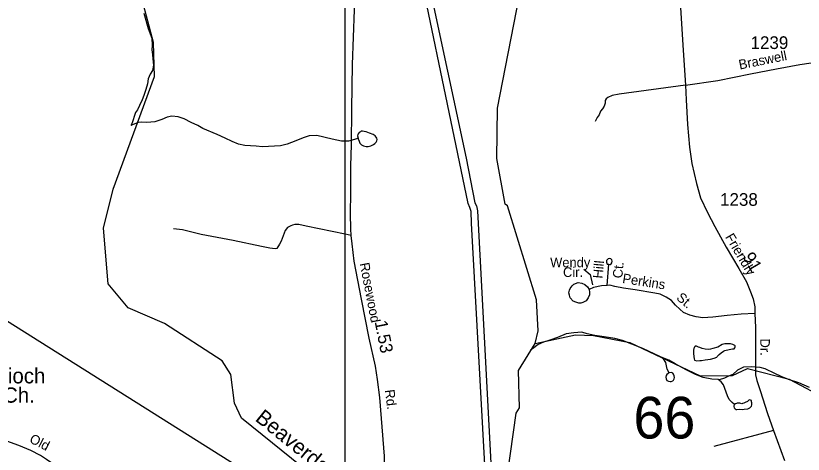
# Model space of a CAD drawing. Extents: x 2206922 to 2357709, y 510027 to 673830.
# Drawn here: x 2263859 to 2271615, y 598510 to 602827 of the extents above; entities that cross this region are included whole.
import ezdxf

# ---------------------------------------------------------------- set-up
doc = ezdxf.new("R2010")
doc.units = 0
for name, color, linetype in [('Exist Cultural Church Label', 7, 'Continuous'), ('Exist Hydrographic Creek Single Shore', 7, 'Continuous'), ('Exist Hydrographic Creek Single Shore Label', 7, 'Continuous'), ('Exist Hydrographic Misc Water Feature', 7, 'Continuous'), ('Exist Road Non-System Type 51', 7, 'Continuous'), ('Exist Road Non-System Type 51 Label', 7, 'Continuous'), ('Exist Road Secondary Mileage Hundredths English Label', 7, 'Continuous'), ('Exist Road Secondary Structure Standard Bridge Number Label', 7, 'Continuous'), ('Exist Road Secondary Type 51 Attributed', 7, 'Continuous'), ('Exist Road Secondary Type 51 Label', 7, 'Continuous'), ('Exist Road Secondary Type 51 Number Label', 7, 'Continuous'), ('Exist Utilities Electrical Transmission Line', 7, 'Continuous'), ('Map Preparation Inset Cut Line', 7, 'Continuous')]:
    doc.layers.add(name, color=color, linetype=linetype)

msp = doc.modelspace()

# ---------------------------------------------------------------- linework, layer by layer
at = {"layer": 'Exist Hydrographic Creek Single Shore'}
for points in [[(2268973.5, 599599.1), (2269005.5, 599726.3), (2268986.6, 600031.7), (2268702.4, 600955.8), (2268677.6, 600972.7), (2268598.4, 601420.4), (2268602.5, 601918.8), (2268816.4, 603013.1), (2268831.6, 603239.1), (2269622.5, 605046.5), (2269645.4, 605219.9)], [(2266778.4, 598305.4), (2266082.5, 598864), (2266014.4, 599013), (2265978.5, 599295.8), (2265893.4, 599428.7), (2265323.6, 599797.7), (2264964.5, 599952.6), (2264770.5, 600186.1), (2264723.4, 600734.7), (2264819.5, 601119.8), (2265225.5, 602229.9), (2265214.5, 602564.7), (2265102.5, 602986.8), (2264730.3, 603601), (2264265.5, 604253.3), (2264229.6, 604503.2), (2264227.3, 604543.3), (2264259.3, 604664.6), (2264265, 604700), (2264253.6, 604725.2), (2264185.5, 604769.8), (2264051.4, 604893.9), (2263717.4, 605022)], [(2268973.5, 599599.1), (2269372.5, 599686.1), (2269547.4, 599679.3), (2269906.5, 599609.7), (2270600.6, 599280.8), (2270917.6, 599284.2), (2271066.4, 599353.3), (2271475.5, 599249.9), (2272245.5, 598840.8)], [(2268671.4, 598096.6), (2268788.5, 598914.1), (2268821.5, 598965.9), (2268809.4, 599333.5), (2268973.5, 599599.1)]]:
    msp.add_lwpolyline(points, dxfattribs=at)
at = {"layer": 'Exist Hydrographic Misc Water Feature'}
for points in [[(2265121.6, 602854), (2265163.2, 602700.6), (2265183.1, 602648.9), (2265197.9, 602604.9), (2265202.4, 602534.9), (2265200.7, 602493), (2265205.2, 602445.2), (2265209.7, 602403.2), (2265214.3, 602341.3), (2265204.6, 602289.2), (2265182.9, 602252.7), (2265163.4, 602206.6), (2265158.1, 602156.7), (2265140.6, 602100.5), (2265119.1, 602042.6), (2265105.2, 602000.4), (2265078.1, 601942.1), (2265058.2, 601902.1), (2265036.9, 601875.7), (2265001.6, 601763.4), (2264993.8, 601747.5)], [(2267232, 601622.7), (2267219.9, 601618.5), (2267216.2, 601616.6), (2267203.9, 601612.3), (2267172.1, 601602.1), (2267136.2, 601593.7), (2267100.1, 601591.4), (2267068.1, 601593), (2266974, 601612.1), (2266825.8, 601648.6), (2266749.7, 601643.9), (2266690.2, 601623.6), (2266618.3, 601596.8), (2266530.9, 601562.1), (2266466.9, 601545.4), (2266289.3, 601535.7), (2266225.2, 601543.3), (2266115.5, 601548.1), (2266053.1, 601561.6), (2265990.8, 601588.7), (2265922.9, 601622.1), (2265842.1, 601657.4), (2265701.9, 601716.3), (2265653.7, 601745.8), (2265585.4, 601775.2), (2265516.7, 601812.3), (2265458.9, 601832), (2265395.1, 601837.1), (2265349, 601828.6), (2265297.3, 601806), (2265229.4, 601783.8), (2265149.3, 601774.8), (2265099.6, 601780.3), (2265063.5, 601776), (2264993.8, 601747.5)], [(2267232, 601622.7), (2267232, 601614.6), (2267240.2, 601592.7), (2267246.7, 601572.6), (2267252.7, 601564.8), (2267264.4, 601557), (2267284.5, 601547), (2267308.7, 601541.4), (2267328.8, 601539.6), (2267356.4, 601548), (2267370.2, 601554), (2267382.5, 601558.3), (2267396.2, 601570), (2267410.2, 601582.5), (2267413.9, 601594.5), (2267418, 601608.5), (2267413.6, 601620.5), (2267407.5, 601630.3), (2267397.7, 601644.4), (2267387.4, 601652), (2267377.8, 601657.9), (2267343.5, 601671.6), (2267309.3, 601683.3), (2267289, 601689.1), (2267273.2, 601691.1), (2267261.3, 601690.9), (2267253.5, 601684.7), (2267241.4, 601676.8), (2267231.4, 601664.5), (2267227.5, 601656.6), (2267226, 601644.7), (2267232, 601622.7)], [(2270232.7, 599457.9), (2270208.9, 599470), (2270035.9, 599552), (2269835.1, 599630.1), (2269759.2, 599649.6), (2269652.8, 599666.5), (2269561.2, 599679.5), (2269485.1, 599695), (2269434.8, 599712.3), (2269355.1, 599705.7), (2269281.1, 599695), (2269193.3, 599658.3), (2269117.8, 599633.6), (2269058, 599613), (2269004.4, 599590.3), (2268948.5, 599548), (2268924.9, 599533.7)], [(2270649, 599438.1), (2270702.7, 599446.6), (2270736.7, 599456.9), (2270762.6, 599467.2), (2270766.3, 599471.2), (2270786.6, 599493.2), (2270807.9, 599509.4), (2270827.8, 599523.5), (2270841.9, 599531.9), (2270883.5, 599540.3), (2270919.4, 599546.6), (2270933.4, 599548.6), (2270939.5, 599556.6), (2270943.4, 599564.9), (2270945.3, 599576.8), (2270941.4, 599580.6), (2270933.6, 599584.6), (2270921.3, 599590.5), (2270897.1, 599596.2), (2270871, 599598.1), (2270842.9, 599597.9), (2270817.3, 599591.6), (2270773.4, 599563.3), (2270725.4, 599550.7), (2270701.9, 599544.5), (2270677.7, 599542), (2270650, 599545.8), (2270619.8, 599551.6), (2270597.3, 599559.4), (2270583.3, 599565.2), (2270563.5, 599573.1), (2270551.6, 599572.9), (2270545.8, 599568.9), (2270539.7, 599564.9), (2270534.1, 599534.9), (2270534.1, 599498.8), (2270540.7, 599448.7), (2270544.8, 599435.2), (2270566.5, 599431.1), (2270594.6, 599431.3), (2270613.1, 599433.8), (2270649, 599438.1)], [(2270294.2, 599310.7), (2270275.8, 599346.3), (2270261.2, 599412.2), (2270232.7, 599457.9)], [(2270776.7, 599245.3), (2270714.8, 599248.6), (2270628.5, 599264), (2270552.6, 599295.3), (2270467.9, 599338.5), (2270353.1, 599399.2), (2270289.3, 599434.8), (2270232.7, 599457.9)], [(2271675, 599167.9), (2271572.5, 599213), (2271470, 599245.8), (2271397.8, 599275), (2271335.7, 599304.6), (2271241.2, 599349.7), (2271191.1, 599363.3), (2271105.2, 599372.2), (2271025.2, 599367.6), (2270965.8, 599338.9), (2270922.3, 599294.8), (2270877.8, 599278.3), (2270840.3, 599260), (2270786.6, 599243.4), (2270776.7, 599245.3)], [(2270294.2, 599310.7), (2270284.2, 599304.5), (2270270, 599296.5), (2270264.7, 599284.3), (2270260.6, 599270.4), (2270264.9, 599252.3), (2270272.5, 599234.5), (2270288.9, 599228.8), (2270303, 599226.6), (2270312.9, 599226.8), (2270328.9, 599232.9), (2270337.1, 599239), (2270342.8, 599253.1), (2270346.5, 599265.1), (2270342.4, 599281.2), (2270338.1, 599297.2), (2270329.9, 599309), (2270316, 599314.7), (2270298.3, 599313), (2270294.2, 599310.7)], [(2270936.6, 598999), (2270914.5, 599018.5), (2270886.2, 599048.3), (2270870.2, 599084.4), (2270828.8, 599193.6), (2270806.6, 599223.8), (2270776.7, 599245.3)], [(2270936.6, 598999), (2270932.5, 598987), (2270931.1, 598980.7), (2270933.2, 598967), (2270943, 598957), (2270953.5, 598951), (2270961.1, 598949), (2270983.2, 598953.4), (2271012.9, 598951.8), (2271033, 598954), (2271068.9, 598958.3), (2271081, 598962.2), (2271089, 598966.3), (2271096.8, 598974.4), (2271104.8, 598982.5), (2271108.9, 598996.5), (2271108.3, 599016.4), (2271106.6, 599024.4), (2271106, 599030.6), (2271104.4, 599038.5), (2271094.3, 599042.5), (2271088.4, 599044.2), (2271080.4, 599042.2), (2271074.2, 599038.2), (2271066.4, 599030.1), (2271042.7, 599019.9), (2271028.5, 599013.9), (2271016.6, 599009.6), (2271008.6, 599007.6), (2270998.4, 599009.5), (2270990.6, 599013.5), (2270980.3, 599013.5), (2270962.5, 599011.3), (2270956.5, 599011), (2270946.5, 599007.2), (2270936.6, 598999)]]:
    msp.add_lwpolyline(points, dxfattribs=at)
at = {"layer": 'Exist Road Non-System Type 51'}
for p, q in [((2267163.1, 600664.5), (2267104.4, 600676.5)), ((2269682.3, 600172.5), (2269700.4, 600380.5)), ((2271321.5, 598744.4), (2270734.7, 598585.3))]:
    msp.add_line(p, q, dxfattribs=at)
for points in [[(2270453.5, 602142.7), (2269800.7, 602054.6), (2269732.7, 602042), (2269690.9, 602023.7), (2269675, 602009.4), (2269665.3, 601991.4), (2269663.6, 601967.4), (2269653.8, 601937.2), (2269638, 601909.2), (2269618.4, 601887), (2269604.7, 601850.9), (2269585, 601826.7), (2269565.3, 601784.5)], [(2267104.4, 600676.5), (2266718.1, 600755.8), (2266647.3, 600770.5), (2266608.2, 600770.5), (2266586.2, 600765.6), (2266566.6, 600758.3), (2266534.9, 600741.2), (2266512.9, 600711.8), (2266474, 600608.1), (2266456.4, 600577.9), (2266429.8, 600535.8), (2266412.7, 600531), (2266361.4, 600538.3), (2266280.6, 600554.3), (2266000.1, 600615.8), (2265684.7, 600672.7), (2265501.5, 600719.2), (2265413.5, 600729)], [(2269700.4, 600380.5), (2269714.5, 600378.8), (2269722.4, 600384.8), (2269730.2, 600394.8), (2269732.2, 600410.8), (2269730, 600424.8), (2269719.9, 600434.6), (2269703.9, 600436.6), (2269692, 600432.4), (2269682.1, 600424.4), (2269678.1, 600416.3), (2269676.2, 600400.3), (2269682.4, 600382.4), (2269700.4, 600380.5)], [(2269504.8, 600132.9), (2269511.1, 600107), (2269509.3, 600080.8), (2269495.7, 600048.7), (2269477.9, 600020.7), (2269444, 600004.4), (2269424.3, 599996.2), (2269404.3, 599996), (2269374.1, 600005.6), (2269350.1, 600017.5), (2269319.8, 600051.1), (2269311.5, 600077.1), (2269307.2, 600098.9), (2269311.1, 600125.1), (2269318.9, 600143.1), (2269338.6, 600169.3), (2269356.5, 600185.3), (2269398.2, 600199.9), (2269434.3, 600194.1), (2269462.4, 600180.4), (2269488.5, 600158.6), (2269504.8, 600132.9)], [(2269682.3, 600172.5), (2269628.5, 600168), (2269548.8, 600151.2), (2269504.8, 600132.9)], [(2271138.2, 599896.2), (2271002.3, 599889), (2270866.5, 599875.7), (2270722.8, 599860.5), (2270626.9, 599853.6), (2270558.9, 599862.8), (2270498.7, 599878.2), (2270436.4, 599905.7), (2270400.1, 599939.4), (2270355.9, 599976.9), (2270317.5, 600022.4), (2270265.2, 600058.1), (2270204.8, 600087.5), (2270152.8, 600097), (2269958.7, 600127.1), (2269844.5, 600146), (2269758.5, 600163.1), (2269708.4, 600174.8), (2269682.3, 600172.5)]]:
    msp.add_lwpolyline(points, dxfattribs=at)
at = {"layer": 'Exist Road Non-System Type 51 Label'}
msp.add_lwpolyline([(2269455.1, 600332.7), (2269515.7, 600279.1), (2269539, 600176.4)], dxfattribs=at)
at = {"layer": 'Exist Road Secondary Type 51 Attributed'}
for points in [[(2270847.8, 604500.4), (2270744.5, 604346.2), (2270622.4, 604163.2), (2270543.9, 604036.2), (2270485.2, 603904.2), (2270387.5, 603606), (2270368, 603520.4), (2270371.4, 603437.3), (2270376.8, 603263.5), (2270406.4, 602905.8), (2270432.3, 602488.2), (2270453.5, 602142.7)], [(2267487.9, 598324.9), (2267490.1, 598492.3), (2267460.8, 598861.4), (2267443.7, 599069.2), (2267421.7, 599245.2), (2267401.1, 599377.5), (2267338.5, 599652.7), (2267262.9, 600037.9), (2267191.5, 600411), (2267172, 600580.8), (2267163.1, 600664.5), (2267160.6, 600728.5), (2267155.2, 600876.4), (2267159.1, 601088.2), (2267160.7, 601346.1), (2267164.6, 601558.2), (2267167.3, 601908), (2267175.3, 602347.9), (2267196.2, 602885.6), (2267216, 603339.7), (2267244, 603969.7)], [(2270453.5, 602142.7), (2270772.1, 602191), (2271095, 602253.8), (2271352.9, 602303.2), (2271581.7, 602348), (2271691.6, 602363.7)], [(2270453.5, 602142.7), (2270462.8, 602000.8), (2270475, 601755), (2270493.1, 601533.3), (2270516.6, 601373.7), (2270562.4, 601176.3), (2270603.7, 601034.7), (2270671.2, 600889.5), (2270742.9, 600752.7), (2270855.1, 600548.5), (2270981.2, 600337.9), (2271054.5, 600205.9), (2271095, 600108.7), (2271121.9, 600041.4), (2271137.7, 599960.2), (2271138.2, 599896.2), (2271145.5, 599756.5), (2271144.1, 599478.6), (2271145.3, 599358.7), (2271145.9, 599292.7), (2271156.3, 599234.9), (2271189.4, 599139.2), (2271261.3, 598912.1), (2271321.5, 598744.4), (2271431.4, 598448.3)], [(2266412.5, 596345.8), (2266363.2, 596377.2), (2266266, 596444.5), (2266180.8, 596513.3), (2266044.7, 596633), (2265905.7, 596767.6), (2265835.4, 596837.9), (2265798.1, 596870.8), (2265647.1, 597027.9), (2265395.9, 597274.7), (2265164.2, 597509.6), (2264881.6, 597778.8), (2264708.2, 597968.8), (2264609.5, 598057.1), (2264510.8, 598152.8), (2264421.1, 598244.1), (2264282.1, 598372.7), (2264223.8, 598416.1), (2264161, 598458), (2264101.2, 598498.4), (2264007, 598546.2), (2263888.9, 598597.1), (2263772.3, 598637.5)]]:
    msp.add_lwpolyline(points, dxfattribs=at)
at = {"layer": 'Exist Utilities Electrical Transmission Line'}
msp.add_line((2267104.4, 597725.3), (2260850.5, 601654.6), dxfattribs=at)
for points in [[(2268566.2, 596655.8), (2268542.8, 597219.3), (2268347.3, 600785.6), (2268344.2, 600899.6), (2268331.8, 600939.5), (2268315.4, 600979.2), (2267687.9, 603993)], [(2267741.8, 603996.8), (2268293.3, 601424.9), (2268379.4, 600985.9), (2268397.7, 600955.9), (2268406.1, 600906.2), (2268629.9, 596682.3)]]:
    msp.add_lwpolyline(points, dxfattribs=at)
at = {"layer": 'Map Preparation Inset Cut Line'}
for p, q in [((2267104.4, 600676.5), (2267104.4, 605243.6)), ((2267104.4, 597725.3), (2267104.4, 600676.5))]:
    msp.add_line(p, q, dxfattribs=at)

# ---------------------------------------------------------------- texts
at = {"layer": 'Exist Cultural Church Label'}
for s, p in [('Antioch', (2263480.9, 599207.6)), ('Ch.', (2263734.4, 599017.5))]:
    msp.add_text(s, height=150, dxfattribs=at).set_placement(p)
at = {"layer": 'Exist Hydrographic Creek Single Shore Label'}
msp.add_text('Beaverdam', height=150, rotation=321.24718, dxfattribs=at).set_placement((2266208.5, 598846.7))
at = {"layer": 'Exist Road Non-System Type 51 Label'}
for s, p in [('Wendy', (2269122, 600351.1)), ('Cir.', (2269248.8, 600255.4))]:
    msp.add_text(s, height=95, dxfattribs=at).set_placement(p)
for s, rotation, p in [('Hill', 85.02745, (2269638.5, 600237.2)), ('Ct.', 85.02745, (2269832.5, 600239.3)), ('Perkins', 351.18464, (2269829, 600197)), ('St.', 319.68785, (2270358.1, 600039.5))]:
    msp.add_text(s, height=95, rotation=rotation, dxfattribs=at).set_placement(p)
at = {"layer": 'Exist Road Secondary Mileage Hundredths English Label'}
for s, rotation, p in [('.91', 300.4607, (2270990.6, 600493.5)), ('1.53', 281.10389, (2267392.8, 599815.2))]:
    msp.add_text(s, height=125, rotation=rotation, dxfattribs=at).set_placement(p)
at = {"layer": 'Exist Road Secondary Structure Standard Bridge Number Label'}
msp.add_text('66', height=410.1, dxfattribs=at).set_placement((2269942.3, 598665))
at = {"layer": 'Exist Road Secondary Type 51 Label'}
for s, rotation, p in [('Braswell', 11.43318, (2270989.5, 602297)), ('Friendly', 300.4607, (2270842.6, 600649.6)), ('Rosewood', 280.83342, (2267246, 600387.7)), ('Dr.', 270.81353, (2271190.5, 599648.8)), ('Rd.', 277.06664, (2267494.1, 599141.9)), ('Old', 332.83847, (2263985.8, 598631.2))]:
    msp.add_text(s, height=95, rotation=rotation, dxfattribs=at).set_placement(p)
at = {"layer": 'Exist Road Secondary Type 51 Number Label'}
for s, p in [('1239', (2271095.7, 602499.6)), ('1238', (2270795.4, 600955.7))]:
    msp.add_text(s, height=125, dxfattribs=at).set_placement(p)

doc.saveas('drawing.dxf')
